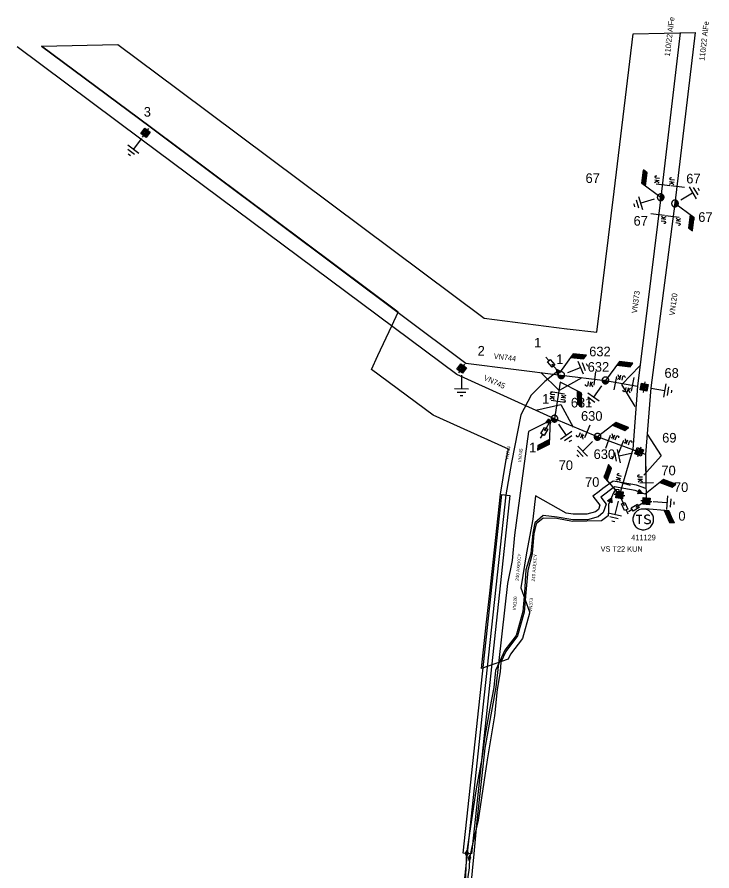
# Model space of a CAD drawing. Extents: x -540182 to -539433, y -1184059 to -1183789.
# Drawn here: x -540181.8 to -540055.5, y -1183944.3 to -1183789 of the extents above; entities that cross this region are included whole.
import ezdxf

# ---------------------------------------------------------------- set-up
doc = ezdxf.new("R2010")
doc.units = 0
for name, color, linetype in [('Default', 7, 'Continuous'), ('Vrstva 1', 7, 'Continuous'), ('Vrstva 11', 7, 'Continuous'), ('Vrstva 12', 7, 'Continuous'), ('Vrstva 13', 7, 'Continuous'), ('Vrstva 14', 7, 'Continuous'), ('Vrstva 15', 7, 'Continuous'), ('Vrstva 16', 7, 'Continuous'), ('Vrstva 18', 7, 'Continuous'), ('Vrstva 19', 7, 'Continuous'), ('Vrstva 2', 7, 'Continuous'), ('Vrstva 20', 7, 'Continuous'), ('Vrstva 25', 7, 'Continuous'), ('Vrstva 26', 7, 'Continuous'), ('Vrstva 27', 7, 'Continuous'), ('Vrstva 3', 7, 'Continuous'), ('Vrstva 35', 7, 'Continuous'), ('Vrstva 4', 7, 'Continuous'), ('Vrstva 5', 7, 'Continuous'), ('Vrstva 52', 7, 'Continuous'), ('Vrstva 6', 7, 'Continuous'), ('Vrstva 7', 7, 'Continuous')]:
    doc.layers.add(name, color=color, linetype=linetype)

# ---------------------------------------------------------------- blocks, each defined once
blk = doc.blocks.new('VN840')
at = {"layer": 'Vrstva 15'}
for points in [[(-0.01, 1.41), (-0.01, -1.09)], [(-1.51, -1.24), (-1.51, -1.15)], [(-1.48, -1.35), (-1.51, -1.24)], [(-1.33, -1.42), (-1.48, -1.35)], [(-1.27, -1.42), (-1.33, -1.42)], [(-1.13, -1.35), (-1.27, -1.42)], [(-1.09, -1.24), (-1.13, -1.35)], [(-1.09, -0.59), (-1.09, -1.24)], [(-0.68, -0.59), (-0.68, -1.42)], [(-0.68, -1.11), (-0.27, -0.59)], [(-0.54, -0.94), (-0.2, -1.42)]]:
    blk.add_lwpolyline(points, dxfattribs=at)
blk = doc.blocks.new('VN860')
at = {"layer": 'Vrstva 15'}
for points in [[(-3.74, 0), (0.01, 2.82)], [(0.01, 2.82), (3.76, 0)]]:
    blk.add_lwpolyline(points, dxfattribs=at)
blk = doc.blocks.new('VN440')
at = {"layer": 'Vrstva 2'}
for points in [[(1.22, 0), (1.21, 0.13), (1.19, 0.25), (1.16, 0.38), (1.11, 0.5), (1.05, 0.61), (0.98, 0.72), (0.9, 0.82), (0.81, 0.91), (0.71, 0.99), (0.6, 1.06), (0.49, 1.12), (0.37, 1.16), (0.25, 1.2), (0.12, 1.22), (-0.01, 1.22), (-0.14, 1.22), (-0.26, 1.2), (-0.39, 1.16), (-0.51, 1.12), (-0.62, 1.06), (-0.73, 0.99), (-0.83, 0.91), (-0.92, 0.82), (-1, 0.72), (-1.07, 0.61), (-1.13, 0.5), (-1.18, 0.38), (-1.21, 0.25), (-1.23, 0.13), (-1.24, 0), (-1.23, -0.13), (-1.21, -0.26), (-1.18, -0.38), (-1.13, -0.5), (-1.07, -0.62), (-1, -0.73), (-0.92, -0.83), (-0.83, -0.92), (-0.73, -1), (-0.62, -1.07), (-0.51, -1.13), (-0.39, -1.17), (-0.26, -1.2), (-0.14, -1.23), (-0.01, -1.23), (0.12, -1.23), (0.25, -1.2), (0.37, -1.17), (0.49, -1.13), (0.6, -1.07), (0.71, -1), (0.81, -0.92), (0.9, -0.83), (0.98, -0.73), (1.05, -0.62), (1.11, -0.5), (1.16, -0.38), (1.19, -0.26), (1.21, -0.13), (1.22, 0)], [(-1.24, 0), (1.22, 0)], [(-1.18, -0.34), (1.1, -0.34)], [(-1.01, -0.63), (0.97, -0.63)], [(-0.74, -0.92), (0.68, -0.92)]]:
    blk.add_lwpolyline(points, dxfattribs=at)
blk = doc.blocks.new('VN870')
at = {"layer": 'Vrstva 4'}
for points in [[(0, -0.25), (0.5, 0), (0, 0.25), (-0.5, 0), (0, -0.25)], [(0.37, 0), (0, 0.19), (-0.36, 0), (0, -0.19), (0.37, 0)], [(0.24, 0), (0, 0.12), (-0.25, 0), (0, -0.12), (0.24, 0)], [(0.12, 0), (0, 0.06), (-0.13, 0), (0, -0.06), (0.12, 0)]]:
    blk.add_lwpolyline(points, dxfattribs=at)
blk = doc.blocks.new('VN890')
at = {"layer": 'Vrstva 4'}
for points in [[(-0.41, 0.41), (0.41, 0)], [(-0.41, -0.41), (-0.41, 0.41)], [(0.41, 0), (-0.41, -0.41)], [(-0.34, 0.31), (0.27, 0), (-0.34, -0.3), (-0.34, 0.31)], [(-0.26, 0.2), (0.1, 0), (-0.26, -0.18), (-0.26, 0.2)], [(-0.19, 0.09), (-0.04, 0), (-0.19, -0.08), (-0.19, 0.09)], [(-0.16, -0.01), (-0.16, 0.03), (-0.13, 0.01), (-0.16, -0.01)]]:
    blk.add_lwpolyline(points, dxfattribs=at)
blk = doc.blocks.new('VN820')
at = {"layer": 'Vrstva 13'}
for points in [[(0, 0), (0, -2.1)], [(-0.32, -1.63), (0.34, -1.63)], [(-0.32, -2.95), (-0.32, -1.63)], [(0.34, -2.95), (-0.32, -2.95)], [(0, -2.1), (-0.12, -1.86)], [(0, -2.1), (0.12, -1.86)], [(0, -2.95), (0, -3.75)], [(0.34, -1.63), (0.34, -2.95)]]:
    blk.add_lwpolyline(points, dxfattribs=at)
blk = doc.blocks.new('VN810')
at = {"layer": 'Vrstva 14'}
for points in [[(0, -1.25), (0, -3.75)], [(1.25, -3.75), (-1.25, -3.75)], [(0.77, -4.37), (-0.8, -4.37)], [(0, -5), (-0.25, -5)], [(0.27, -5), (0, -5)]]:
    blk.add_lwpolyline(points, dxfattribs=at)
blk = doc.blocks.new('VN610')
at = {"layer": 'Vrstva 6'}
for points in [[(1.88, 0), (1.87, 0.2), (1.84, 0.39), (1.79, 0.58), (1.72, 0.77), (1.63, 0.94), (1.52, 1.11), (1.4, 1.26), (1.26, 1.4), (1.1, 1.53), (0.94, 1.63), (0.76, 1.72), (0.58, 1.8), (0.39, 1.85), (0.19, 1.88), (-0.01, 1.89), (-0.21, 1.88), (-0.4, 1.85), (-0.59, 1.8), (-0.78, 1.72), (-0.95, 1.63), (-1.12, 1.53), (-1.27, 1.4), (-1.41, 1.26), (-1.54, 1.11), (-1.64, 0.94), (-1.73, 0.77), (-1.8, 0.58), (-1.86, 0.39), (-1.89, 0.2), (-1.9, 0), (-1.89, -0.2), (-1.86, -0.39), (-1.8, -0.58), (-1.73, -0.77), (-1.64, -0.95), (-1.54, -1.11), (-1.41, -1.27), (-1.27, -1.41), (-1.12, -1.53), (-0.95, -1.64), (-0.78, -1.73), (-0.59, -1.8), (-0.4, -1.85), (-0.21, -1.88), (-0.01, -1.89), (0.19, -1.88), (0.39, -1.85), (0.58, -1.8), (0.76, -1.73), (0.94, -1.64), (1.1, -1.53), (1.26, -1.41), (1.4, -1.27), (1.52, -1.11), (1.63, -0.95), (1.72, -0.77), (1.79, -0.58), (1.84, -0.39), (1.87, -0.2), (1.88, 0)], [(-1.27, 0.78), (-0.26, 0.78)], [(-0.76, 0.78), (-0.76, -0.79)], [(1.19, 0.66), (0.94, 0.78), (0.62, 0.78), (0.37, 0.66), (0.24, 0.47), (0.24, 0.4), (0.37, 0.22), (1.12, -0.16), (1.25, -0.32), (1.25, -0.48), (1.12, -0.67), (0.87, -0.79), (0.62, -0.79), (0.49, -0.73), (0.24, -0.6)]]:
    blk.add_lwpolyline(points, dxfattribs=at)
blk = doc.blocks.new('VN001')
at = {"layer": 'Default'}
for p, q in [((1.79, 3.13), (4.2, 3.13)), ((1.82, 3.18), (4.23, 3.18)), ((1.85, 3.23), (4.26, 3.23)), ((1.87, 3.28), (4.29, 3.28)), ((1.9, 3.33), (4.32, 3.33)), ((1.93, 3.38), (4.35, 3.38)), ((1.96, 3.43), (4.37, 3.43)), ((1.99, 3.48), (4.4, 3.48)), ((2.02, 3.53), (4.43, 3.53)), ((2.05, 3.58), (4.46, 3.58)), ((2.07, 3.63), (4.49, 3.63)), ((2.1, 3.68), (4.52, 3.68)), ((2.13, 3.73), (2.54, 3.73)), ((1.73, 3.03), (4.14, 3.03)), ((1.76, 3.08), (4.17, 3.08))]:
    blk.add_line(p, q, dxfattribs=at)
blk.add_lwpolyline([(2.13, 3.73), (0, 0)], dxfattribs=at)
blk.add_lwpolyline([(4.55, 3.73), (2.13, 3.73), (1.7, 2.98), (4.12, 2.99)], close=True, dxfattribs=at)
blk = doc.blocks.new('VN470')
at = {"layer": 'Vrstva 2'}
for points in [[(-1.23, 1.22), (1.23, 1.22)], [(-1.23, -1.23), (-1.23, 1.22)], [(-0.92, 0.9), (0.92, 0.9)], [(-0.92, -0.95), (-0.92, 0.9)], [(-0.61, 0.61), (0.61, 0.61)], [(-0.61, -0.62), (-0.61, 0.61)], [(-0.31, -0.27), (-0.31, 0.34)], [(-0.31, 0.34), (0.31, 0.34)], [(0, 1.22), (0, 1.97)], [(0.31, 0.34), (0.31, -0.27)], [(0.61, 0.61), (0.61, -0.62)], [(0.92, 0.9), (0.92, -0.95)], [(1.23, 1.22), (1.23, -1.23)], [(1.23, -1.23), (-1.23, -1.23)], [(0.92, -0.95), (-0.92, -0.95)], [(0.61, -0.62), (-0.61, -0.62)], [(0.31, -0.27), (-0.31, -0.27)], [(0, -1.23), (0, -1.98)]]:
    blk.add_lwpolyline(points, dxfattribs=at)

msp = doc.modelspace()

# ---------------------------------------------------------------- linework, layer by layer
at = {"layer": 'Vrstva 1'}
for points in [[(-540061.26, -1183791.91), (-540064.83, -1183821.78)], [(-540058.59, -1183791.85), (-540062.23, -1183822.93)], [(-540177.36, -1183794.34), (-540157.62, -1183809.02), (-540100.23, -1183851.93), (-540082.89, -1183854.15)], [(-540084.14, -1183862.05), (-540101.85, -1183854.04), (-540159.34, -1183811.21), (-540181.81, -1183794.43)], [(-540064.83, -1183821.78), (-540069.07, -1183856.15)], [(-540062.23, -1183822.93), (-540066.59, -1183856.47), (-540067.58, -1183868.57)], [(-540082.89, -1183854.15), (-540074.86, -1183855.1)], [(-540074.86, -1183855.1), (-540069.07, -1183856.15)], [(-540069.07, -1183856.15), (-540069.9, -1183867.59), (-540072.3, -1183875.92)], [(-540076.3, -1183865.34), (-540084.14, -1183862.05)], [(-540067.58, -1183868.57), (-540076.3, -1183865.34)], [(-540067.58, -1183868.57), (-540067.48, -1183877.05)]]:
    msp.add_lwpolyline(points, dxfattribs=at)
at = {"layer": 'Vrstva 20'}
msp.add_lwpolyline([(-540093.72, -1183875.84), (-540092.22, -1183876), (-540099.23, -1183941.17), (-540100.73, -1183941.01)], close=True, dxfattribs=at)
at = {"layer": 'Vrstva 35'}
msp.add_lwpolyline([(-540058.59, -1183791.85), (-540062.23, -1183822.93), (-540066.59, -1183856.47), (-540067.58, -1183868.57), (-540067.51, -1183874.77), (-540069.22, -1183874.14), (-540071.66, -1183873.7), (-540073.45, -1183873.38), (-540075.32, -1183874.77), (-540076, -1183875.28), (-540077.14, -1183876.12), (-540075.87, -1183877.79), (-540076.12, -1183878.54), (-540076.68, -1183879.01), (-540078.26, -1183879.43), (-540080.74, -1183879.43), (-540082, -1183879.22), (-540087.59, -1183876.06), (-540088.05, -1183880.33), (-540089.2, -1183886.46), (-540090.25, -1183892.78), (-540088.66, -1183897.16), (-540088.68, -1183897.42), (-540089.94, -1183902), (-540092.11, -1183904.88), (-540092.52, -1183905.74), (-540097.39, -1183907.45), (-540096.53, -1183899.55), (-540095.91, -1183893.8), (-540093.96, -1183875.78), (-540092.95, -1183869.84), (-540092.51, -1183867.59), (-540106.2, -1183861.41), (-540117.37, -1183853.08), (-540116.22, -1183850.59), (-540113.72, -1183845.2), (-540112.56, -1183842.71), (-540157.62, -1183809.02), (-540177.36, -1183794.34), (-540163.51, -1183794.05), (-540152.54, -1183802.21), (-540096.93, -1183843.78), (-540081.9, -1183845.71), (-540081.85, -1183845.71), (-540081.81, -1183845.72), (-540076.43, -1183846.35), (-540073.28, -1183820.78), (-540069.84, -1183792.09)], close=True, dxfattribs=at)
at = {"layer": 'Vrstva 4'}
msp.add_lwpolyline([(-540067.64, -1183878.43), (-540067.65, -1183878.5)], dxfattribs=at)
at = {"layer": 'Vrstva 5'}
for points in [[(-540083.24, -1183853.72), (-540083.51, -1183853.39), (-540085.89, -1183855.3), (-540088.39, -1183857.77), (-540090.26, -1183861.36), (-540091.97, -1183870.02), (-540092.97, -1183875.92), (-540097.15, -1183914.52), (-540099.98, -1183941.09), (-540109, -1184024.53)], [(-540084.83, -1183862.39), (-540088.84, -1183864.39), (-540091.38, -1183883.23), (-540091.81, -1183887.85), (-540092.67, -1183892.03), (-540094.81, -1183910.88), (-540096.81, -1183921.97), (-540098.27, -1183935.14), (-540098.77, -1183941.17), (-540106.98, -1184024.6)], [(-540067.66, -1183875.78), (-540068.48, -1183875.48), (-540069.48, -1183875.11), (-540073.2, -1183874.44), (-540075.73, -1183876.32), (-540074.76, -1183877.6), (-540075.26, -1183879.12), (-540076.2, -1183879.92), (-540078.13, -1183880.43), (-540080.82, -1183880.43), (-540083.64, -1183879.97), (-540086.19, -1183879.65), (-540087.7, -1183880.98), (-540088.08, -1183882.88), (-540088.44, -1183886.57), (-540089.31, -1183889.55), (-540089.56, -1183893.63), (-540089.89, -1183897.13), (-540091.07, -1183901.46), (-540093.15, -1183904.15), (-540094.12, -1183906.25), (-540094.83, -1183907.85), (-540095.18, -1183910.93), (-540095.9, -1183914.67), (-540096.78, -1183919.82), (-540097.33, -1183923.85), (-540098.37, -1183929.31), (-540100.1, -1183941.06), (-540100.25, -1183943.62), (-540100.34, -1183946.52)], [(-540072.3, -1183875.92), (-540072.39, -1183874.96), (-540073.07, -1183874.95), (-540073.4, -1183875.53), (-540073.95, -1183876.79), (-540074.33, -1183877.66), (-540074.32, -1183878.63), (-540074.38, -1183879.73), (-540075.56, -1183880.64), (-540080.83, -1183880.73), (-540083.68, -1183880.22), (-540086.19, -1183880.15), (-540087.47, -1183881.14), (-540087.87, -1183882.96), (-540088.21, -1183886.63), (-540089, -1183889.66), (-540089.32, -1183893.65), (-540089.67, -1183897.24), (-540090.85, -1183901.55), (-540092.97, -1183904.36), (-540093.89, -1183906.31), (-540094.01, -1183908.05), (-540094.53, -1183911.31), (-540095.03, -1183916.07), (-540096.36, -1183924.07), (-540098.01, -1183935.04), (-540099.19, -1183940.21), (-540099.56, -1183941.92), (-540099.63, -1183943.7), (-540100.07, -1183946.57)]]:
    msp.add_lwpolyline(points, dxfattribs=at)
at = {"layer": 'Vrstva 52'}
msp.add_lwpolyline([(-540083.07, -1183855.41), (-540084.14, -1183862.05)], dxfattribs=at)

# ---------------------------------------------------------------- block references
at = {"layer": 'Vrstva 11'}
for p, rotation in [((-540064.83, -1183821.79), 82.97227774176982), ((-540062.24, -1183822.93), -96.68660830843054), ((-540083.24, -1183853.72), -5.999733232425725), ((-540074.86, -1183855.09), -7.101947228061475), ((-540083.07, -1183855.4), -87.72943615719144), ((-540084.83, -1183862.39), -153.43188067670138), ((-540076.3, -1183865.34), -22.750372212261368), ((-540072.3, -1183875.92), 70.46426947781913), ((-540067.66, -1183875.78), -21.324651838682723), ((-540067.64, -1183878.43), -65.32766515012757)]:
    msp.add_blockref('VN001', p, dxfattribs=dict(at, rotation=rotation))
at = {"layer": 'Vrstva 13'}
for name, p, xscale, yscale, rotation in [('VN470', (-540158.45, -1183810.09), 0.5, 0.5, -36.67322223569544), ('VN440', (-540064.83, -1183821.79), 0.5, 0.5000000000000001, 83.18003612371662), ('VN440', (-540062.23, -1183822.93), 0.5000000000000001, 0.5, 83.31339162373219), ('VN470', (-540101, -1183852.91), 0.5, 0.5, -36.70481391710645), ('VN440', (-540082.89, -1183854.15), 0.5000000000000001, 0.5, -7.29050283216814), ('VN440', (-540074.86, -1183855.1), 0.49999999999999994, 0.49999999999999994, -9.332689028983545), ('VN470', (-540067.82, -1183856.31), 0.5, 0.5, -9.787200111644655), ('VN440', (-540084.14, -1183862.05), 0.49999999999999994, 0.5000000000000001, -24.336652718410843), ('VN440', (-540076.3, -1183865.34), 0.5000000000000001, 0.4999999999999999, -22.742711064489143), ('VN470', (-540068.73, -1183868.08), 0.5, 0.5, -19.910569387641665), ('VN470', (-540072.3, -1183875.92), 0.49999999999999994, 0.5000000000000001, 83.7276794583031), ('VN470', (-540067.43, -1183877.04), 0.49999999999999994, 0.5000000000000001, 85.55201129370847)]:
    msp.add_blockref(name, p, dxfattribs=dict(at, xscale=xscale, yscale=yscale, rotation=rotation))
at = {"layer": 'Vrstva 15'}
for p, rotation in [((-540158.44, -1183810.09), -36.70430563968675), ((-540062.24, -1183822.93), 121.15838890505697), ((-540064.84, -1183821.78), -72.80636665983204), ((-540082.89, -1183854.15), 111.85910001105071), ((-540101, -1183852.91), -0.40961389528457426), ((-540074.86, -1183855.09), -35.751658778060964), ((-540067.82, -1183856.31), 80.62684993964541), ((-540084.14, -1183862.05), 35.055088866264), ((-540076.3, -1183865.34), -45.93649661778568), ((-540068.73, -1183868.08), -77.77036665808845), ((-540067.43, -1183877.04), 85.7612873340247), ((-540072.29, -1183875.85), -13.4590577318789)]:
    msp.add_blockref('VN810', p, dxfattribs=dict(at, rotation=rotation))
at = {"layer": 'Vrstva 16'}
for p, rotation in [((-540083.24, -1183853.72), -139.15197230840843), ((-540084.83, -1183862.39), -30.549394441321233), ((-540072.3, -1183875.92), 23.304758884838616), ((-540067.48, -1183877.05), -59.41805263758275)]:
    msp.add_blockref('VN820', p, dxfattribs=dict(at, rotation=rotation))
at = {"layer": 'Vrstva 18'}
for name, p, rotation in [('VN840', (-540064.57, -1183819.55), -96.81996392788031), ('VN840', (-540061.88, -1183819.86), -96.68660839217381), ('VN840', (-540065.22, -1183824.94), 82.97227774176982), ('VN840', (-540062.54, -1183825.26), 82.60627224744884), ('VN840', (-540076.84, -1183854.86), -6.709422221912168), ('VN860', (-540069.07, -1183856.15), 83.47401392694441), ('VN860', (-540082.89, -1183854.15), 172.70949730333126), ('VN840', (-540073.02, -1183855.43), 169.69515281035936), ('VN840', (-540069.97, -1183855.98), -10.304847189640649), ('VN860', (-540084.14, -1183862.05), -24.33591103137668), ('VN840', (-540083.63, -1183858.9), -99.17129168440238), ('VN840', (-540083.38, -1183857.35), 80.82870831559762), ('VN840', (-540078.23, -1183864.53), -22.747369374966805), ('VN840', (-540074.32, -1183866.07), 159.6336333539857), ('VN840', (-540071.93, -1183866.96), 159.6336333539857), ('VN860', (-540067.58, -1183868.57), -94.68643888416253), ('VN840', (-540071.69, -1183873.8), -106.12612222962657), ('VN840', (-540067.52, -1183873.77), -88.7345583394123)]:
    msp.add_blockref(name, p, dxfattribs=dict(at, rotation=rotation))
at = {"layer": 'Vrstva 19'}
for name, p, rotation in [('VN890', (-540083.51, -1183853.39), 129.20720282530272), ('VN890', (-540085.32, -1183862.62), -153.54718882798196), ('VN890', (-540068.48, -1183875.48), -20.21026897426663), ('VN890', (-540073.95, -1183876.79), 66.41296956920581), ('VN870', (-540100.1, -1183941.06), 83.920286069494), ('VN870', (-540099.98, -1183941.09), 83.920286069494), ('VN870', (-540099.56, -1183941.92), 83.920286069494)]:
    msp.add_blockref(name, p, dxfattribs=dict(at, rotation=rotation))
at = {"layer": 'Vrstva 25'}
msp.add_blockref('VN610', (-540068, -1183880.36), dxfattribs=at)

# ---------------------------------------------------------------- texts
at = {"layer": 'Vrstva 12'}
for s, p in [('67', (-540078.49, -1183819.2)), ('67', (-540058, -1183826.27)), ('1', (-540087.83, -1183849.11)), ('632', (-540077.82, -1183850.71)), ('631', (-540081.16, -1183860.01)), ('630', (-540079.31, -1183862.43)), ('1', (-540088.74, -1183868.16)), ('70', (-540083.37, -1183871.39)), ('70', (-540064.7, -1183872.34)), ('0', (-540061.61, -1183880.6))]:
    msp.add_text(s, height=1.75, dxfattribs=at).set_placement(p)
at = {"layer": 'Vrstva 14'}
for s, p in [('3', (-540158.78, -1183807.15)), ('67', (-540060.18, -1183819.28)), ('67', (-540069.76, -1183826.96)), ('2', (-540098.1, -1183850.58)), ('1', (-540083.81, -1183852.1)), ('632', (-540078.1, -1183853.51)), ('68', (-540064.14, -1183854.62)), ('1', (-540086.37, -1183859.32)), ('69', (-540064.56, -1183866.39)), ('630', (-540077.02, -1183869.38)), ('70', (-540078.58, -1183874.44)), ('70', (-540062.42, -1183875.38))]:
    msp.add_text(s, height=1.75, dxfattribs=at).set_placement(p)
at = {"layer": 'Vrstva 2'}
for rotation, p in [(83.18, (-540063.17, -1183796.24)), (83.313, (-540056.87, -1183797.01))]:
    msp.add_text('110/22 AlFe', height=1, rotation=rotation, dxfattribs=at).set_placement(p)
at = {"layer": 'Vrstva 26'}
msp.add_text('411129', height=1, dxfattribs=at).set_placement((-540070.18, -1183884.16))
at = {"layer": 'Vrstva 27'}
msp.add_text('VS T22 KUN', height=1, dxfattribs=at).set_placement((-540075.75, -1183886.23))
at = {"layer": 'Vrstva 3'}
for s, rotation, p in [('VN373', 82.972, (-540069.12, -1183842.93)), ('VN120', 82.606, (-540062.31, -1183843.36)), ('VN744', 352.709, (-540095.22, -1183851.13)), ('VN745', 335.664, (-540097.09, -1183854.97))]:
    msp.add_text(s, height=1, rotation=rotation, dxfattribs=at).set_placement(p)
at = {"layer": 'Vrstva 6'}
for rotation, p in [(84.428, (-540090.65, -1183891.55)), (85.415, (-540087.7, -1183891.65))]:
    msp.add_text('240 AXEKCY', height=0.6, rotation=rotation, dxfattribs=at).set_placement(p)
at = {"layer": 'Vrstva 7'}
for s, rotation, p in [('VN744', 78.83, (-540092.56, -1183869.6)), ('VN745', 82.322, (-540090.2, -1183870.03)), ('VN120', 84.614, (-540091.16, -1183896.93)), ('VN373', 84.432, (-540088.25, -1183897.21))]:
    msp.add_text(s, height=0.6, rotation=rotation, dxfattribs=at).set_placement(p)

doc.saveas('drawing.dxf')
